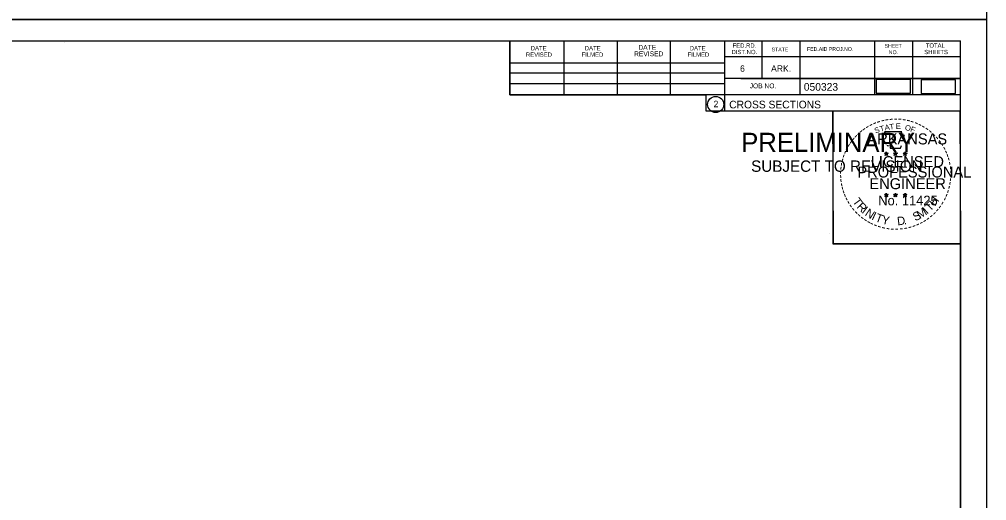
# Model space of a CAD drawing. Extents: x 1360146 to 1361431, y 631444 to 632352.
# Drawn here: x 1360303.1 to 1360479.7, y 631569.6 to 631657.5 of the extents above; entities that cross this region are included whole.
import ezdxf

# ---------------------------------------------------------------- set-up
doc = ezdxf.new("R2010")
doc.units = 0
for name, color, linetype in [('Default', 7, 'Continuous'), ('R_Border', 7, 'Continuous'), ('R_Border PE', 7, 'Continuous'), ('R_Border Prem', 7, 'Continuous'), ('R_No Plot', 7, 'Continuous')]:
    doc.layers.add(name, color=color, linetype=linetype)

msp = doc.modelspace()

# ---------------------------------------------------------------- linework, layer by layer
at = {"layer": 'Default'}
for points in [[(1360459.54, 631644.01), (1360465.79, 631644.01), (1360465.79, 631646.48), (1360459.54, 631646.48)], [(1360467.76, 631643.95), (1360474.01, 631643.95), (1360474.01, 631646.43), (1360467.76, 631646.43)]]:
    msp.add_lwpolyline(points, close=True, dxfattribs=at)
at = {"layer": 'R_Border'}
for p, q in [((1360158.77, 631653.6), (1360474.95, 631653.6)), ((1360311.29, 631653.34), (1360311.29, 631653.34)), ((1360311.29, 631653.34), (1360311.29, 631653.34)), ((1360392.69, 631643.72), (1360392.69, 631653.6)), ((1360402.55, 631643.72), (1360402.55, 631653.4)), ((1360412.31, 631643.72), (1360412.31, 631653.4)), ((1360421.99, 631643.72), (1360421.99, 631653.4)), ((1360431.85, 631653.6), (1360431.85, 631640.8)), ((1360438.69, 631653.6), (1360438.69, 631646.66)), ((1360445.63, 631653.6), (1360445.63, 631643.72)), ((1360459.21, 631653.6), (1360459.21, 631643.72)), ((1360466.15, 631653.6), (1360466.15, 631643.72)), ((1360474.95, 631448.14), (1360474.95, 631653.6)), ((1360474.95, 631650.66), (1360431.85, 631650.66)), ((1360474.95, 631650.68), (1360474.95, 631650.68)), ((1360392.69, 631649.58), (1360431.85, 631649.58)), ((1360392.69, 631647.72), (1360431.85, 631647.72)), ((1360474.95, 631646.66), (1360431.85, 631646.66)), ((1360434.81, 631646.66), (1360474.95, 631646.66)), ((1360392.69, 631643.72), (1360392.69, 631645.78)), ((1360392.69, 631645.78), (1360431.85, 631645.78)), ((1360474.95, 631643.72), (1360392.69, 631643.72)), ((1360431.85, 631640.8), (1360474.95, 631640.8))]:
    msp.add_line(p, q, dxfattribs=at)
msp.add_circle((1360430.24, 631641.94), 1.47, dxfattribs=at)
at = {"layer": 'R_Border PE'}
for p, q in [((1360461.04, 631633.06), (1360461.38, 631632.95)), ((1360461.04, 631633.06), (1360461.29, 631633.01)), ((1360461.04, 631633.06), (1360461.27, 631632.94)), ((1360461.17, 631632.65), (1360461.38, 631632.95)), ((1360461.17, 631632.65), (1360461.29, 631632.9)), ((1360461.17, 631632.65), (1360461.38, 631632.87)), ((1360461.38, 631633.31), (1360461.34, 631633.06)), ((1360461.38, 631632.95), (1360461.38, 631633.31)), ((1360461.38, 631633.31), (1360461.43, 631633.06)), ((1360461.73, 631633.06), (1360461.38, 631632.95)), ((1360461.6, 631632.65), (1360461.38, 631632.95)), ((1360461.6, 631632.65), (1360461.38, 631632.87)), ((1360461.73, 631633.06), (1360461.45, 631633.01)), ((1360461.6, 631632.65), (1360461.46, 631632.94)), ((1360461.73, 631633.06), (1360461.53, 631632.96)), ((1360462.71, 631633.06), (1360463.05, 631632.95)), ((1360462.71, 631633.06), (1360462.96, 631633.01)), ((1360462.71, 631633.06), (1360462.94, 631632.94)), ((1360462.84, 631632.65), (1360463.05, 631632.95)), ((1360462.84, 631632.65), (1360462.96, 631632.9)), ((1360462.84, 631632.65), (1360463.05, 631632.87)), ((1360463.05, 631633.31), (1360463.01, 631633.06)), ((1360463.05, 631632.95), (1360463.05, 631633.31)), ((1360463.05, 631633.31), (1360463.1, 631633.06)), ((1360463.4, 631633.06), (1360463.05, 631632.95)), ((1360463.27, 631632.65), (1360463.05, 631632.95)), ((1360463.27, 631632.65), (1360463.05, 631632.87)), ((1360463.4, 631633.06), (1360463.12, 631633.01)), ((1360463.27, 631632.65), (1360463.13, 631632.94)), ((1360463.4, 631633.06), (1360463.2, 631632.96)), ((1360464.47, 631633.05), (1360464.82, 631632.94)), ((1360464.47, 631633.05), (1360464.72, 631633)), ((1360464.47, 631633.05), (1360464.71, 631632.93)), ((1360464.6, 631632.64), (1360464.82, 631632.94)), ((1360464.6, 631632.64), (1360464.73, 631632.88)), ((1360464.6, 631632.64), (1360464.82, 631632.86)), ((1360464.82, 631633.3), (1360464.78, 631633.05)), ((1360464.82, 631632.94), (1360464.82, 631633.3)), ((1360464.82, 631633.3), (1360464.87, 631633.05)), ((1360465.17, 631633.05), (1360464.82, 631632.94)), ((1360465.03, 631632.64), (1360464.82, 631632.94)), ((1360465.03, 631632.64), (1360464.82, 631632.85)), ((1360465.17, 631633.05), (1360464.88, 631633)), ((1360465.03, 631632.64), (1360464.89, 631632.93)), ((1360465.17, 631633.05), (1360464.96, 631632.95)), ((1360461.03, 631625.49), (1360461.38, 631625.38)), ((1360461.03, 631625.49), (1360461.28, 631625.44)), ((1360461.03, 631625.49), (1360461.27, 631625.36)), ((1360461.16, 631625.08), (1360461.38, 631625.38)), ((1360461.16, 631625.08), (1360461.29, 631625.32)), ((1360461.16, 631625.08), (1360461.38, 631625.3)), ((1360461.38, 631625.74), (1360461.34, 631625.49)), ((1360461.38, 631625.38), (1360461.38, 631625.74)), ((1360461.38, 631625.74), (1360461.43, 631625.49)), ((1360461.73, 631625.49), (1360461.38, 631625.38)), ((1360461.59, 631625.08), (1360461.38, 631625.38)), ((1360461.59, 631625.08), (1360461.38, 631625.29)), ((1360461.73, 631625.49), (1360461.44, 631625.44)), ((1360461.59, 631625.08), (1360461.46, 631625.37)), ((1360461.73, 631625.49), (1360461.52, 631625.38)), ((1360462.7, 631625.49), (1360463.05, 631625.38)), ((1360462.7, 631625.49), (1360462.95, 631625.44)), ((1360462.7, 631625.49), (1360462.94, 631625.36)), ((1360462.83, 631625.08), (1360463.05, 631625.38)), ((1360462.83, 631625.08), (1360462.96, 631625.32)), ((1360462.83, 631625.08), (1360463.05, 631625.3)), ((1360463.05, 631625.74), (1360463.01, 631625.49)), ((1360463.05, 631625.38), (1360463.05, 631625.74)), ((1360463.05, 631625.74), (1360463.1, 631625.49)), ((1360463.4, 631625.49), (1360463.05, 631625.38)), ((1360463.26, 631625.08), (1360463.05, 631625.38)), ((1360463.26, 631625.08), (1360463.05, 631625.29)), ((1360463.4, 631625.49), (1360463.11, 631625.44)), ((1360463.26, 631625.08), (1360463.13, 631625.37)), ((1360463.4, 631625.49), (1360463.19, 631625.38)), ((1360464.47, 631625.48), (1360464.82, 631625.37)), ((1360464.47, 631625.48), (1360464.72, 631625.43)), ((1360464.47, 631625.48), (1360464.7, 631625.35)), ((1360464.6, 631625.07), (1360464.82, 631625.37)), ((1360464.6, 631625.07), (1360464.73, 631625.31)), ((1360464.6, 631625.07), (1360464.81, 631625.29)), ((1360464.82, 631625.73), (1360464.78, 631625.48)), ((1360465.03, 631625.07), (1360464.81, 631625.28)), ((1360464.82, 631625.37), (1360464.82, 631625.73)), ((1360464.82, 631625.73), (1360464.87, 631625.48)), ((1360465.16, 631625.48), (1360464.82, 631625.37)), ((1360465.03, 631625.07), (1360464.82, 631625.37)), ((1360465.16, 631625.48), (1360464.88, 631625.43)), ((1360465.03, 631625.07), (1360464.89, 631625.36)), ((1360465.16, 631625.48), (1360464.96, 631625.37))]:
    msp.add_line(p, q, dxfattribs=at)
for points in [[(1360461.08, 631636.94), (1360461.35, 631636.11)], [(1360464.59, 631636.02), (1360464.73, 631636.3), (1360464.04, 631636.28), (1360464.19, 631636.94), (1360461.08, 631636.94)], [(1360461.57, 631634.51), (1360461.57, 631634.43), (1360462.13, 631634.41), (1360462.08, 631633.94), (1360463.95, 631633.94), (1360464.15, 631634.47)], [(1360461.38, 631633.31), (1360461.6, 631632.65), (1360461.04, 631633.06), (1360461.73, 631633.06), (1360461.17, 631632.65), (1360461.38, 631633.31)], [(1360463.05, 631633.31), (1360463.27, 631632.65), (1360462.71, 631633.06), (1360463.4, 631633.06), (1360462.84, 631632.65), (1360463.05, 631633.31)], [(1360464.82, 631633.3), (1360465.03, 631632.64), (1360464.47, 631633.05), (1360465.17, 631633.05), (1360464.6, 631632.64), (1360464.82, 631633.3)], [(1360461.38, 631625.74), (1360461.59, 631625.08), (1360461.03, 631625.49), (1360461.73, 631625.49), (1360461.16, 631625.08), (1360461.38, 631625.74)], [(1360463.05, 631625.74), (1360463.26, 631625.08), (1360462.7, 631625.49), (1360463.4, 631625.49), (1360462.83, 631625.08), (1360463.05, 631625.74)], [(1360464.82, 631625.73), (1360465.03, 631625.07), (1360464.47, 631625.48), (1360465.16, 631625.48), (1360464.6, 631625.07), (1360464.82, 631625.73)]]:
    msp.add_lwpolyline(points, dxfattribs=at)
for centre, radius in [((1360461.38, 631632.95), 0.172), ((1360461.38, 631632.95), 0.145), ((1360461.38, 631632.95), 0.116), ((1360461.38, 631632.95), 0.0991), ((1360461.38, 631632.95), 0.0747), ((1360461.38, 631632.95), 0.0495), ((1360461.38, 631632.95), 0.0296), ((1360463.05, 631632.95), 0.172), ((1360463.05, 631632.95), 0.145), ((1360463.05, 631632.95), 0.116), ((1360463.05, 631632.95), 0.0991), ((1360463.05, 631632.95), 0.0747), ((1360463.05, 631632.95), 0.0495), ((1360463.05, 631632.95), 0.0296), ((1360464.82, 631632.94), 0.172), ((1360464.82, 631632.94), 0.145), ((1360464.82, 631632.94), 0.116), ((1360464.82, 631632.94), 0.0991), ((1360464.82, 631632.94), 0.0747), ((1360464.82, 631632.94), 0.0495), ((1360464.82, 631632.94), 0.0296), ((1360461.38, 631625.37), 0.172), ((1360461.38, 631625.37), 0.145), ((1360461.38, 631625.37), 0.116), ((1360461.38, 631625.37), 0.0991), ((1360461.38, 631625.37), 0.0747), ((1360461.38, 631625.37), 0.0495), ((1360461.38, 631625.37), 0.0296), ((1360463.05, 631625.37), 0.172), ((1360463.05, 631625.37), 0.145), ((1360463.05, 631625.37), 0.116), ((1360463.05, 631625.37), 0.0991), ((1360463.05, 631625.37), 0.0747), ((1360463.05, 631625.37), 0.0495), ((1360463.05, 631625.37), 0.0296), ((1360464.82, 631625.36), 0.172), ((1360464.82, 631625.36), 0.145), ((1360464.82, 631625.36), 0.116), ((1360464.82, 631625.36), 0.0991), ((1360464.82, 631625.36), 0.0747), ((1360464.82, 631625.36), 0.0495), ((1360464.82, 631625.36), 0.0296)]:
    msp.add_circle(centre, radius, dxfattribs=at)
at = {"layer": 'R_No Plot'}
for p, q in [((1360146.37, 631657.5), (1360479.7, 631657.5)), ((1360450.99, 631618.35), (1360450.99, 631618.35))]:
    msp.add_line(p, q, dxfattribs=at)
for points in [[(1360146.36, 631870.84), (1360479.7, 631870.84), (1360479.7, 631657.5), (1360146.36, 631657.5)], [(1360146.36, 631657.5), (1360479.7, 631657.5), (1360479.7, 631444.16), (1360146.36, 631444.16)], [(1360392.69, 631653.6), (1360392.69, 631643.72), (1360428.42, 631643.72), (1360428.42, 631640.8), (1360451.62, 631640.8), (1360451.62, 631616.47), (1360474.95, 631616.47), (1360474.95, 631448.14), (1360158.77, 631448.14), (1360158.77, 631653.6)], [(1360451.62, 631640.8), (1360474.83, 631640.8), (1360474.95, 631616.47), (1360451.74, 631616.47)]]:
    msp.add_lwpolyline(points, close=True, dxfattribs=at)

# ---------------------------------------------------------------- texts
at = {"layer": 'R_Border'}
for s, height, p in [('REVISED', 0.782, (1360395.61, 631650.66)), ('DATE', 0.782, (1360396.49, 631651.84)), ('FILMED', 0.782, (1360405.77, 631650.66)), ('DATE', 0.782, (1360406.35, 631651.84)), ('REVISED', 0.879, (1360415.35, 631650.76)), ('DATE', 0.879, (1360416.13, 631651.94)), ('FILMED', 0.782, (1360425.11, 631650.66)), ('DATE', 0.782, (1360425.51, 631651.84)), ('DIST.NO.', 0.782, (1360433.13, 631651.14)), ('FED.RD.', 0.782, (1360433.33, 631652.32)), ('STATE', 0.684, (1360440.45, 631651.64)), ('FED.AID PROJ.NO.', 0.684, (1360446.91, 631651.74)), ('SHEET', 0.684, (1360461.07, 631652.32)), ('NO.', 0.684, (1360461.85, 631651.14)), ('SHEETS', 0.782, (1360468.31, 631651.14)), ('TOTAL', 0.782, (1360468.59, 631652.32)), ('6', 1.17, (1360434.69, 631647.92)), ('ARK.', 1.172, (1360440.35, 631647.92)), ('JOB NO.', 0.879, (1360436.45, 631644.9)), ('050323', 1.4, (1360446.33, 631644.46)), ('2', 1.17, (1360429.85, 631641.45)), ('CROSS SECTIONS', 1.4, (1360432.71, 631641.23))]:
    msp.add_text(s, height=height, rotation=360, dxfattribs=at).set_placement(p)
at = {"layer": 'R_Border PE'}
for s, height, rotation, p in [('-', 1.6, 13.6301, (1360460.57, 631638.31)), ('-', 1.6, 10.2193, (1360461.25, 631638.47)), ('-', 1.6, 5.8968, (1360461.98, 631638.58)), ('-', 1.6, 0.1862, (1360462.75, 631638.65)), ('-', 1.6, 357.743, (1360463.48, 631638.64)), ('-', 1.6, 352.1617, (1360464.22, 631638.58)), ('-', 1.6, 347.2049, (1360464.94, 631638.47)), ('-', 1.6, 38.9507, (1360456.91, 631636.34)), ('-', 1.6, 36.2317, (1360457.38, 631636.71)), ('-', 1.6, 34.0636, (1360457.96, 631637.11)), ('-', 1.6, 28.7918, (1360458.56, 631637.48)), ('-', 1.6, 24.3072, (1360459.19, 631637.8)), ('S', 1, 21.594, (1360459.43, 631636.62)), ('-', 1.6, 19.1761, (1360459.82, 631638.06)), ('T', 1, 16.4036, (1360460.35, 631636.95)), ('A', 1, 11.2132, (1360461.17, 631637.2)), ('T', 1, 6.0228, (1360462.02, 631637.36)), ('E', 1, 0.8323, (1360463.13, 631637.47)), ('O', 1, 350.4515, (1360464.73, 631637.26)), ('F', 1, 340.0707, (1360465.68, 631637.04)), ('-', 1.6, 342.3362, (1360465.57, 631638.31)), ('-', 1.6, 337.8551, (1360466.31, 631638.09)), ('-', 1.6, 334.1211, (1360466.94, 631637.82)), ('-', 1.6, 329.6409, (1360467.52, 631637.53)), ('-', 1.6, 325.8627, (1360468.16, 631637.17)), ('-', 1.6, 320.5297, (1360468.77, 631636.75)), ('-', 1.6, 50.6142, (1360455.62, 631634.95)), ('-', 1.6, 48.423, (1360456.03, 631635.44)), ('-', 1.6, 42.9622, (1360456.47, 631635.92)), ('ARKANSAS', 2, 360, (1360457.93, 631634.65)), ('-', 1.6, 315.5786, (1360469.37, 631636.26)), ('-', 1.6, 309.8797, (1360469.94, 631635.71)), ('-', 1.6, 62.8713, (1360454.57, 631633.25)), ('-', 1.6, 58.0706, (1360454.88, 631633.86)), ('-', 1.6, 54.2325, (1360455.21, 631634.39)), ('-', 1.6, 306.6522, (1360470.47, 631635.11)), ('-', 1.4, 303.6753, (1360470.95, 631634.54)), ('-', 1.6, 299.6684, (1360471.27, 631633.93)), ('-', 1.6, 75.461, (1360453.9, 631631.29)), ('-', 1.6, 72.3945, (1360454.09, 631632.01)), ('-', 1.6, 67.7743, (1360454.31, 631632.64)), ('LICENSED', 2, 360, (1360458.53, 631630.5)), ('DWB', 0.01, 360, (1360461.37, 631632.94)), ('DWB', 0.01, 360, (1360463.04, 631632.94)), ('DWB', 0.01, 360, (1360464.81, 631632.93)), ('-', 1.6, 294.6628, (1360471.59, 631633.32)), ('-', 1.6, 290.5728, (1360471.85, 631632.74)), ('-', 1.6, 285.1233, (1360472.09, 631632.16)), ('-', 1.6, 85.1863, (1360453.69, 631629.89)), ('-', 1.6, 81.2013, (1360453.76, 631630.58)), ('PROFESSIONAL', 2, 360, (1360456.1, 631628.6)), ('-', 1.6, 280.5493, (1360472.29, 631631.42)), ('-', 1.6, 276.5962, (1360472.45, 631630.65)), ('-', 1.6, 94.1959, (1360453.7, 631628.46)), ('-', 1.6, 89.0622, (1360453.66, 631629.19)), ('ENGINEER', 2, 360, (1360458.29, 631626.47)), ('-', 1.6, 263.5172, (1360472.52, 631628.63)), ('-', 1.6, 274.3301, (1360472.51, 631629.93)), ('-', 1.6, 269.9407, (1360472.54, 631629.3)), ('-', 1.6, 98.9479, (1360453.77, 631627.79)), ('-', 1.6, 101.7149, (1360453.91, 631627.06)), ('-', 1.6, 105.4578, (1360454.07, 631626.47)), ('-', 1.6, 255.7626, (1360472.34, 631627.3)), ('-', 1.6, 260.9953, (1360472.45, 631627.98)), ('-', 1.6, 109.0874, (1360454.28, 631625.84)), ('-', 1.6, 114.0643, (1360454.54, 631625.24)), ('-', 1.6, 115.7289, (1360454.84, 631624.62)), ('T', 1.54, 306.0406, (1360455.14, 631624.21)), ('No. 11425', 1.757, 360, (1360459.92, 631623.52)), ('DWB', 0.01, 360, (1360461.37, 631625.37)), ('DWB', 0.01, 360, (1360463.04, 631625.37)), ('DWB', 0.01, 360, (1360464.8, 631625.36)), ('H', 1.54, 54.6088, (1360470.26, 631623.25)), ('-', 1.6, 244.6197, (1360471.68, 631625.28)), ('-', 1.6, 247.8887, (1360471.94, 631625.91)), ('-', 1.6, 252.8681, (1360472.16, 631626.58)), ('-', 1.6, 120.4471, (1360455.2, 631624.04)), ('-', 1.6, 125.8934, (1360455.6, 631623.47)), ('R', 1.54, 314.005, (1360455.9, 631623.17)), ('I', 1.54, 321.9694, (1360456.8, 631622.23)), ('M', 1.54, 32.6563, (1360467.52, 631620.98)), ('I', 1.54, 42.1136, (1360468.81, 631621.83)), ('T', 1.54, 46.6444, (1360469.37, 631622.31)), ('-', 1.6, 233.8452, (1360470.88, 631623.87)), ('-', 1.6, 239.0712, (1360471.28, 631624.53)), ('-', 1.6, 130.7181, (1360456.06, 631622.92)), ('-', 1.6, 134.2238, (1360456.58, 631622.38)), ('-', 1.6, 138.9338, (1360457.11, 631621.91)), ('-', 1.6, 144.6463, (1360457.66, 631621.51)), ('N', 1.54, 326.5002, (1360457.37, 631621.76)), ('I', 1.54, 335.3603, (1360458.58, 631620.98)), ('T', 1.54, 339.8912, (1360459.24, 631620.65)), ('Y', 1.54, 347.8556, (1360460.46, 631620.2)), ('D', 1.54, 6.3969, (1360463.44, 631619.85)), ('S', 1.54, 26.9312, (1360466.69, 631620.58)), ('-', 1.6, 221.0851, (1360469.45, 631622.24)), ('-', 1.6, 225.7653, (1360469.97, 631622.74)), ('-', 1.6, 231.2538, (1360470.45, 631623.31)), ('-', 1.6, 148.0898, (1360458.22, 631621.14)), ('-', 1.6, 151.5704, (1360458.8, 631620.81)), ('-', 1.6, 154.6002, (1360459.32, 631620.56)), ('-', 1.6, 158.5612, (1360459.95, 631620.31)), ('-', 1.6, 162.7983, (1360460.63, 631620.1)), ('.', 1.54, 13.7642, (1360464.63, 631619.97)), ('-', 1.6, 195.4743, (1360465.89, 631620.2)), ('-', 1.6, 200.7184, (1360466.56, 631620.44)), ('-', 1.6, 204.2516, (1360467.18, 631620.71)), ('-', 1.6, 207.3568, (1360467.81, 631621.03)), ('-', 1.6, 212.2491, (1360468.37, 631621.38)), ('-', 1.6, 215.7363, (1360468.9, 631621.76)), ('-', 1.6, 167.5555, (1360461.35, 631619.93)), ('-', 1.6, 173.1155, (1360462.12, 631619.82)), ('-', 1.6, 176.5183, (1360462.87, 631619.77)), ('-', 1.6, 181.5918, (1360463.61, 631619.79)), ('-', 1.6, 185.8167, (1360464.42, 631619.87)), ('-', 1.6, 191.2858, (1360465.16, 631620))]:
    msp.add_text(s, height=height, rotation=rotation, dxfattribs=at).set_placement(p)
at = {"layer": 'R_Border Prem'}
for s, height, p in [('PRELIMINARY', 3.5, (1360434.9, 631633.27)), ('DWB', 0.01, (1360435.65, 631635.12)), ('SUBJECT TO REVISION', 2.0751, (1360436.71, 631629.64))]:
    msp.add_text(s, height=height, rotation=360, dxfattribs=at).set_placement(p)

doc.saveas('drawing.dxf')
